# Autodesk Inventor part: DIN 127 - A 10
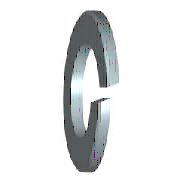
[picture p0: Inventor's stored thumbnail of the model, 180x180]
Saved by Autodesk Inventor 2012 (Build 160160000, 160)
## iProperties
Created: 2004-09
Part Number: DIN 127 - A 10
Material: Standard
Description: Federring
Vendor: Autodesk Inc.
Document SubType Name: Modeling
Standard: DIN 127
Designer: Greiling
Size Designation: A 10
Density: 1 g/cm^3
Checked By: Jürgen Kronas
Stock Number: 10-10018
Company: CAD-Verlag
Classification: un/spsc 31161811
Author: Juergen Kronas
Revision Number: 8
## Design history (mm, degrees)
sketch "Skizze1"
  geometry: C1 r 9.05 at (0, 0); C2 r 5.35 at (0, 0); 1 further point
  constraints: 2 centre point, 2 coincident
  dimensions: "d0" = 10.7 diameter of C2 (= SD1); "d1" = 18.1 diameter of C1 (= SD2)
extrude "Körper" new body sketch "Skizze1" distance "d2" = 2.2 (= SD); taper "d3" = 0 deg
sketch "Skizze2"
  geometry: L1 (0, -5.35)-(0, 5.35) reference; L2 (2.2, 9.05)-(2.2, -9.05) reference; L3 (-0.6, 0)-(7.8, 0) reference; L4 (0, -0.44)-(2.2, 0.83); L5 (0, 0.44)-(2.2, 1.71)
  constraints: 4 end point, 4 point on line, 1 parallel
  dimensions: "d4" = 0.44 distance from line of L3 L4.start (= 0.2 x SD); "d5" = 0.44 distance from line of L3 L5.start (= 0.2 x SD); "d6" = 60 deg angle of L2 L4 (= FAWI)
extrude "Schnitt" cut sketch "Skizze2" stored distance "d7" = 2.2 (= SD); taper "d8" = 0 deg
node "Volumenkörper1"
node "Volumenkörpern"
node "Oberflächenkörpern"
other parameters: "SD1" = 10.7 [user parameter; used in 1 equation term], "SD2" = 18.1 [user parameter; used in 1 equation term], "SD" = 2.2 [user parameter; used in 4 equation terms], "FAWI" = 60 deg [user parameter; used in 1 equation term], "d9" = 0, "d10" = 0
